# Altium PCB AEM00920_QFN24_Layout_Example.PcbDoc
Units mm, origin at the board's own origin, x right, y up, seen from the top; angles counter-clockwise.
Board outline 76 x 49 mm, 4 copper layers (Component Side, Ground Plane, Power Plane, Solder Side), stack 1.563 mm thick; 11 components, 22 nets, 46 pads, 22 vias.
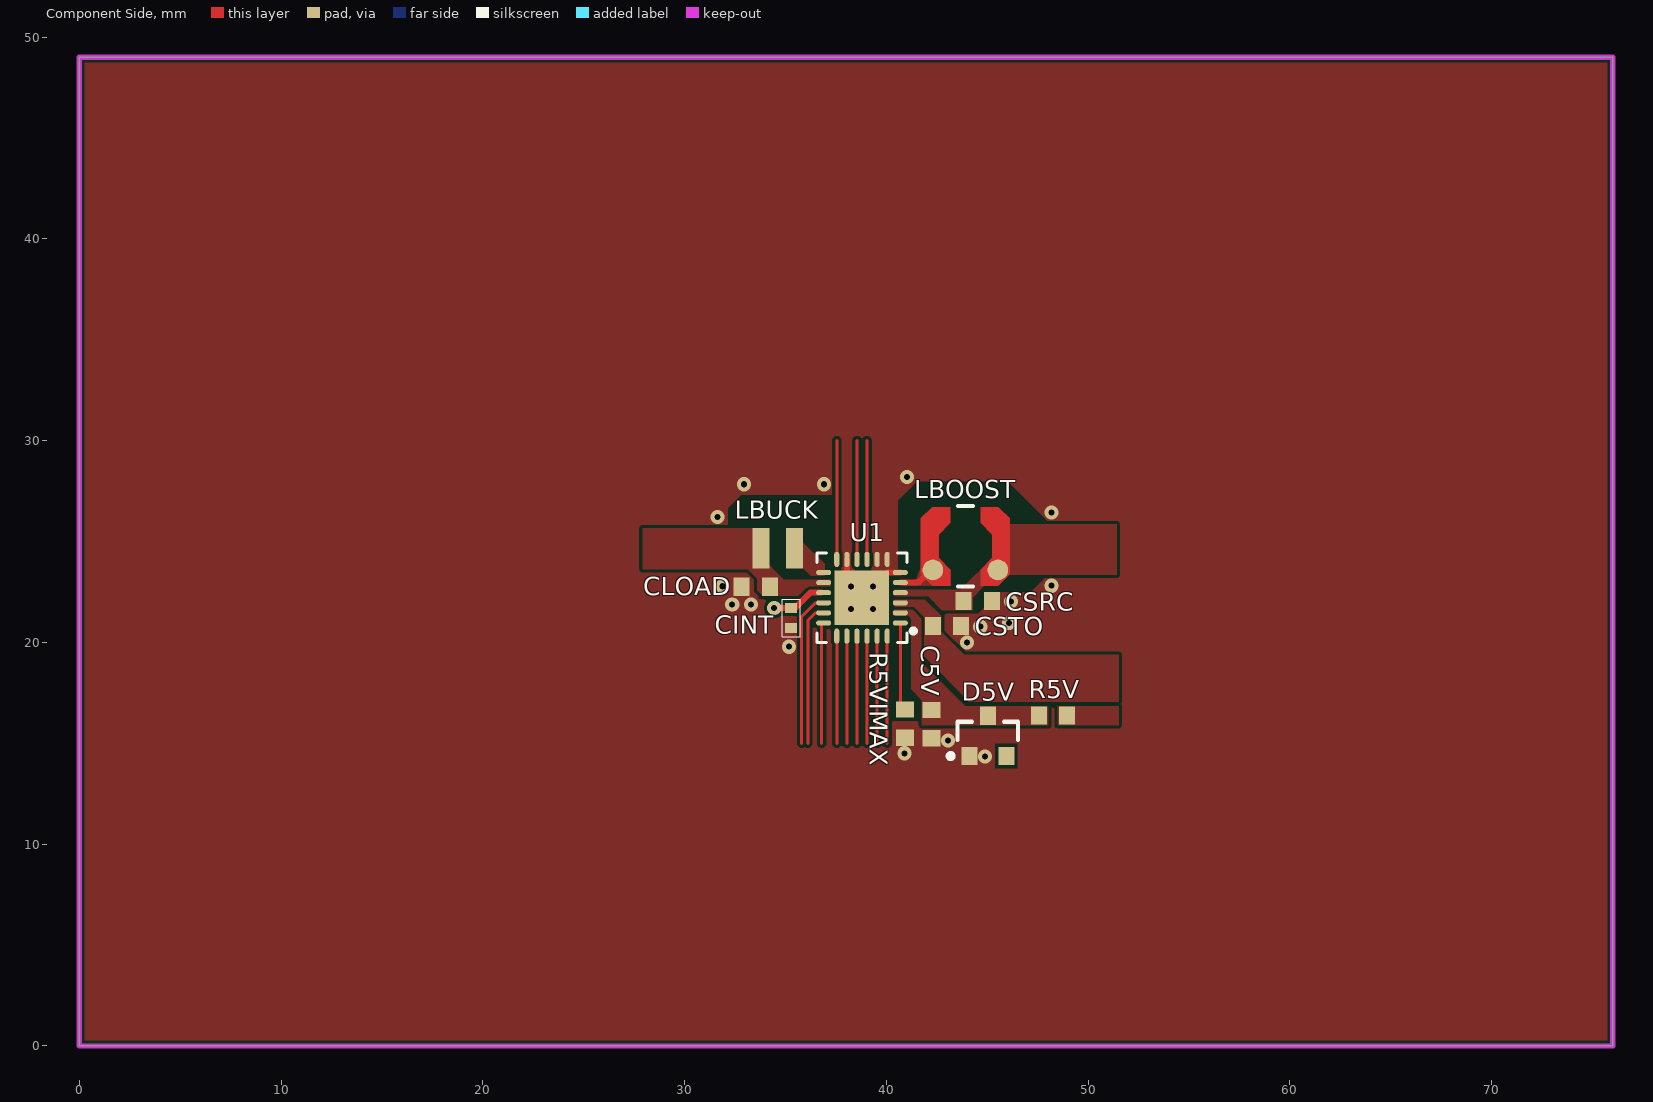
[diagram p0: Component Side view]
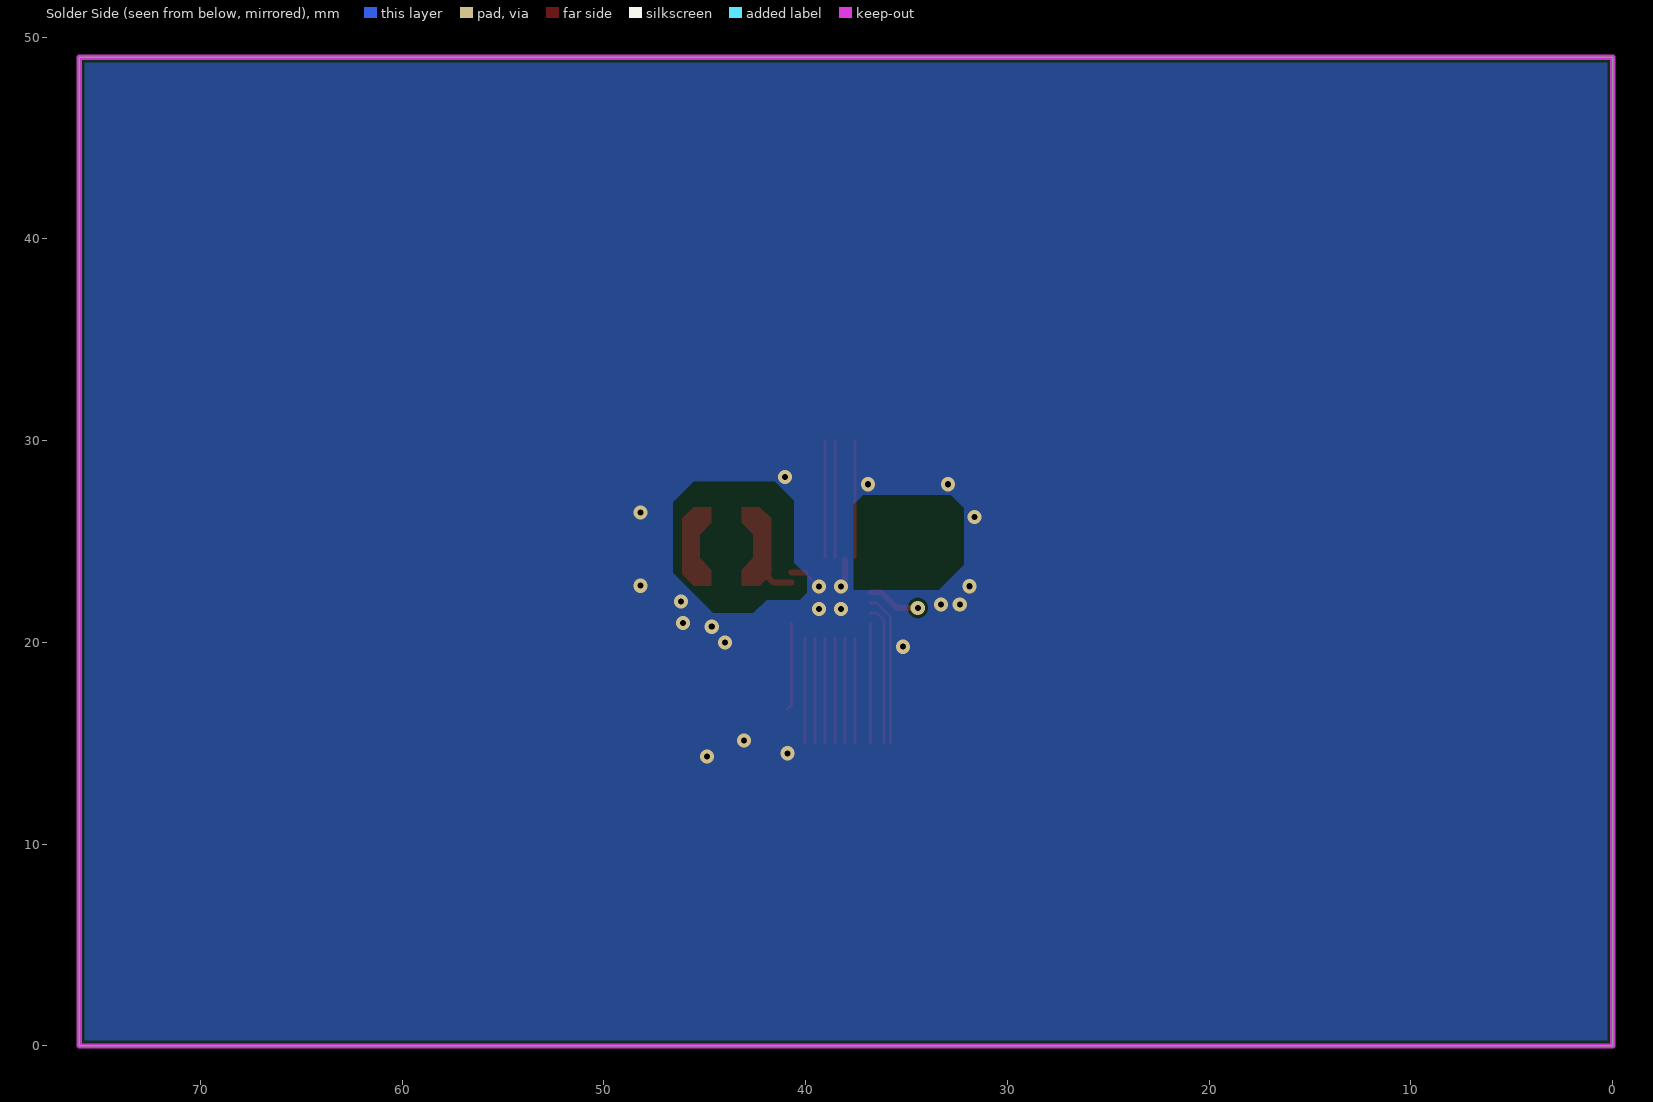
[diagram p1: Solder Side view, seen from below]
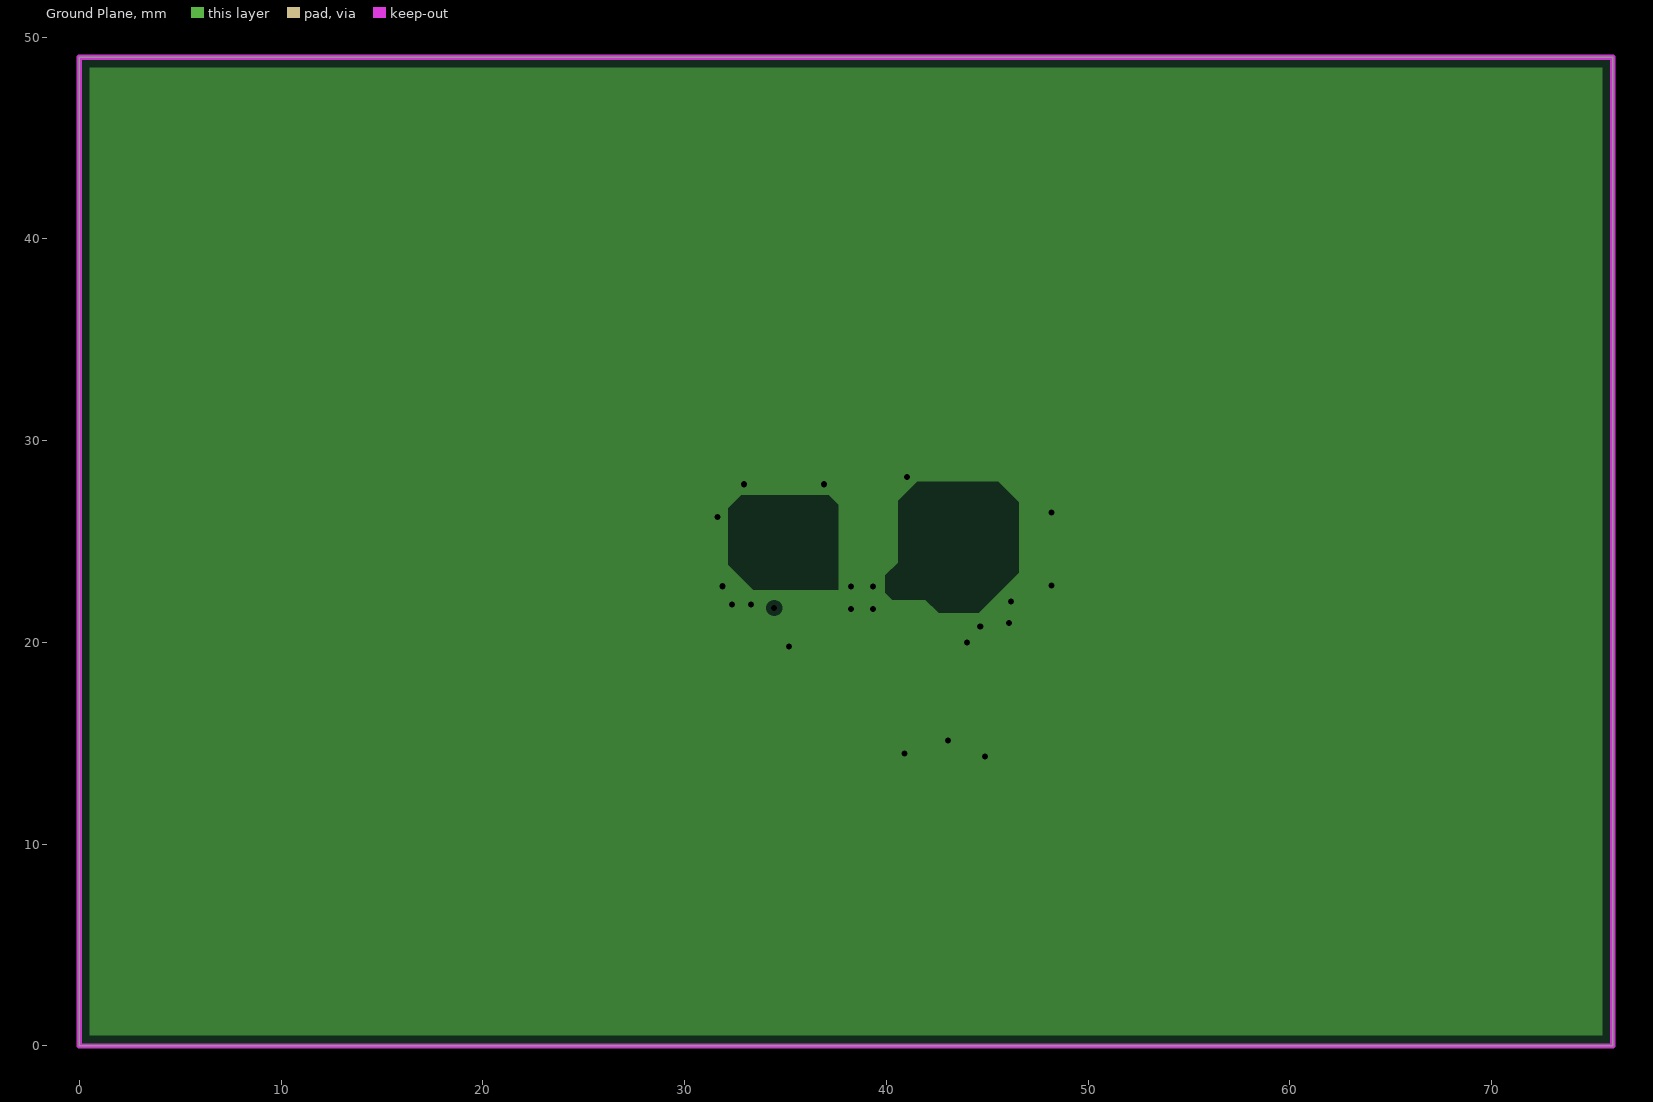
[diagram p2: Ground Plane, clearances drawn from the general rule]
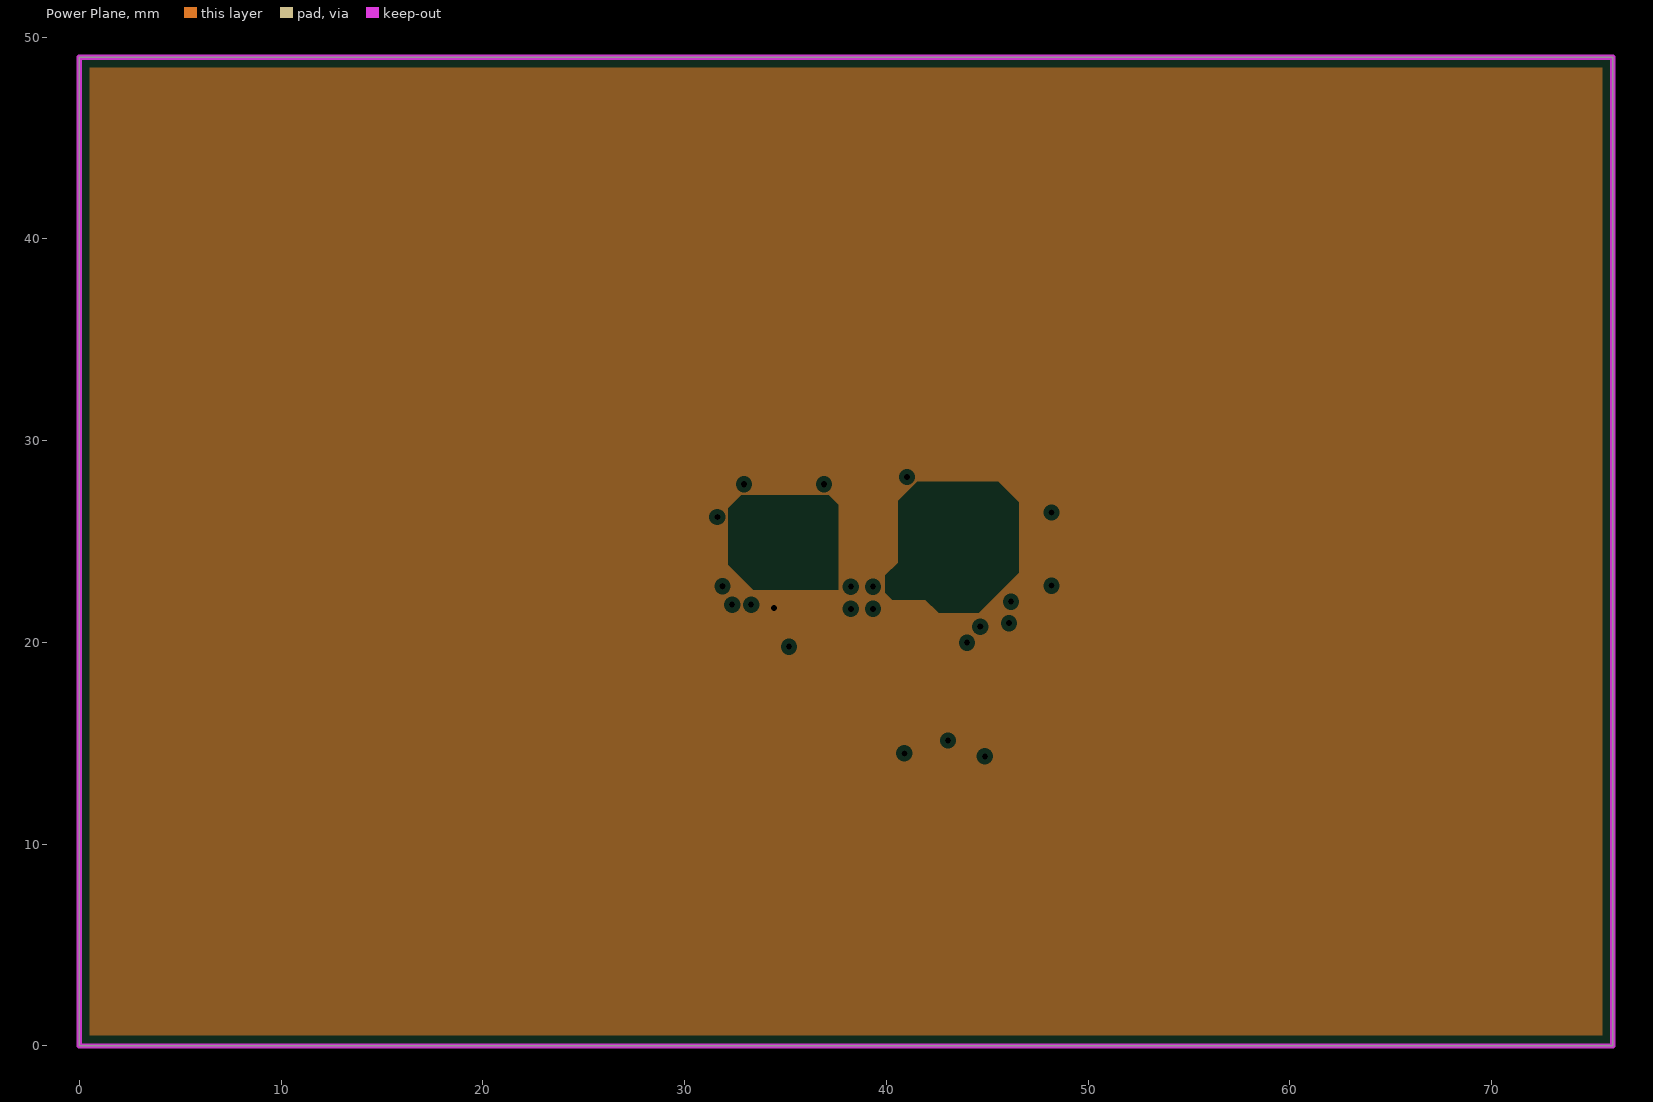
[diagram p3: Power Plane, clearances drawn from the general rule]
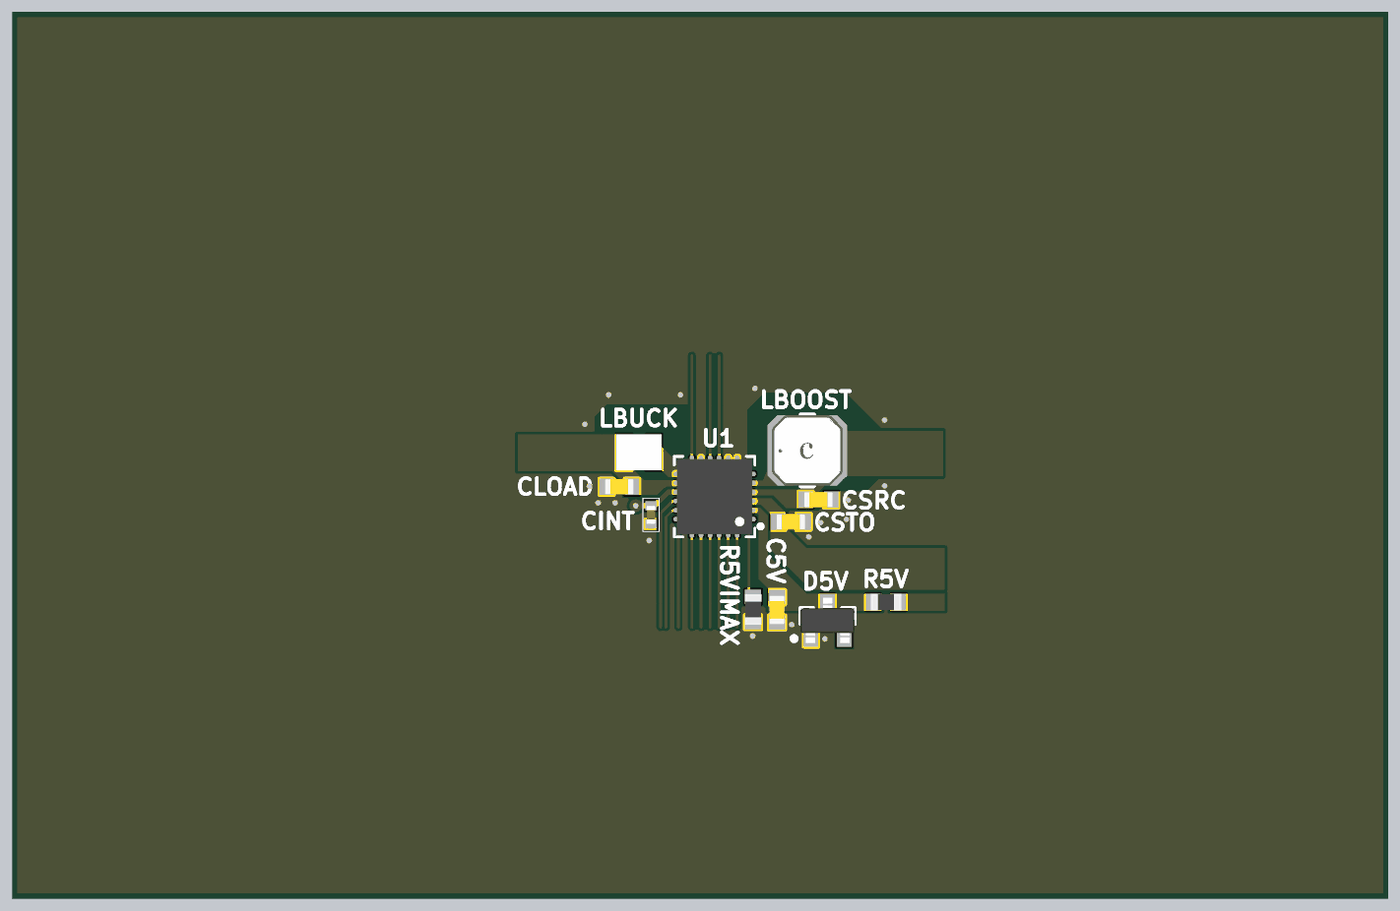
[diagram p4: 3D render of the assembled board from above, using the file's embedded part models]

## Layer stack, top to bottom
Top Solder: solder mask 0.0102, Solder Resist, Dk 3.5
Component Side: signal copper 0.0356
Dielectric 1: prepreg 0.36, Prepreg 7628, Dk 4.2
Ground Plane: plane copper 0.036, net GND
Dielectric 3: core 0.7, Core, Dk 4.2
Power Plane: plane copper 0.036, net VINT
Dielectric 4: prepreg 0.36, Prepreg 7628, Dk 4.2
Solder Side: signal copper 0.0356
Bottom Solder: solder mask 0.0102, Solder Resist, Dk 3.5

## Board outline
0,0 0,49 76,49 76,0

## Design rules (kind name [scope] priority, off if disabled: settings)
Clearance Clearance_SW [InNet('SWBOOST') or InNet('SWBUCK') vs InNet('GND')] p1: gap=0.15 ignorepadtopadclearanceinfootprint=FALSE except(0.5: Arc-Poly Track-Poly SMDPad-Poly THPad-Poly Via-Poly Fill-Poly Poly-Poly Poly-Region)
Clearance [All] p2: gap=0.15 ignorepadtopadclearanceinfootprint=FALSE
ComponentClearance ComponentClearance_DIL [HasFootprint('DIL_PAD') vs HasFootprint('DIL_PAD')] p1: gap=0 collisioncheckmode=3 verticalgap=0 showdistances=FALSE
ComponentClearance [All] p2: gap=0.254 collisioncheckmode=3 verticalgap=0.254 showdistances=FALSE
DiffPairsRouting [All] p1: maxlimit=0.254 minlimit=0.254 mostfreqgap=0.254 toplayer_minwidth=0.381 toplayer_maxwidth=0.381 toplayer_prefwidth=0.381 bottomlayer_minwidth=0.381 bottomlayer_maxwidth=0.381 bottomlayer_prefwidth=0.381 substack1={24748C9E-C2FE-4590-BE0C-AD6E21E98903} toplayer_{24748c9e-c2fe-4590-be0c-ad6e21e98903}_minwidth=0.381 toplayer_{24748c9e-c2fe-4590-be0c-ad6e21e98903}_maxwidth=0.381 toplayer_{24748c9e-c2fe-4590-be0c-ad6e21e98903}_prefwidth=0.381 bottomlayer_{24748c9e-c2fe-4590-be0c-ad6e21e98903}_minwidth=0.381 bottomlayer_{24748c9e-c2fe-4590-be0c-ad6e21e98903}_maxwidth=0.381 bottomlayer_{24748c9e-c2fe-4590-be0c-ad6e21e98903}_prefwidth=0.381 substack2={CAEF0C9C-1F67-4FFA-A1CA-0FD6FF6C2F90} toplayer_{caef0c9c-1f67-4ffa-a1ca-0fd6ff6c2f90}_minwidth=0.381 toplayer_{caef0c9c-1f67-4ffa-a1ca-0fd6ff6c2f90}_maxwidth=0.381 toplayer_{caef0c9c-1f67-4ffa-a1ca-0fd6ff6c2f90}_prefwidth=0.381 bottomlayer_{caef0c9c-1f67-4ffa-a1ca-0fd6ff6c2f90}_minwidth=0.381 bottomlayer_{caef0c9c-1f67-4ffa-a1ca-0fd6ff6c2f90}_maxwidth=0.381 bottomlayer_{caef0c9c-1f67-4ffa-a1ca-0fd6ff6c2f90}_prefwidth=0.381 substack3={D99B185B-21CD-406C-9F05-D1849F64E374} toplayer_{d99b185b-21cd-406c-9f05-d1849f64e374}_minwidth=0.381 toplayer_{d99b185b-21cd-406c-9f05-d1849f64e374}_maxwidth=0.381 toplayer_{d99b185b-21cd-406c-9f05-d1849f64e374}_prefwidth=0.381 bottomlayer_{d99b185b-21cd-406c-9f05-d1849f64e374}_minwidth=0.381 bottomlayer_{d99b185b-21cd-406c-9f05-d1849f64e374}_maxwidth=0.381 bottomlayer_{d99b185b-21cd-406c-9f05-d1849f64e374}_prefwidth=0.381 maxuncoupledlength=12.7
HoleToHoleClearance [All] p1: gap=0.2 allowstackedmicrovias=TRUE
MinimumAnnularRing [All] p1: minimumring=0.15
MinimumSolderMaskSliver [All] p1: minsoldermaskwidth=0
PlaneClearance [All] p1: clearance=0.254
PlaneConnect "Plane Force direct connect" [InComponent('M1') or InComponent('M2') or InComponent('M3') or InComponent('M4') or InComponent('TP1') or InComponent('TP2') or InComponent('TP3')] p1: planeconnectstyle=Direct reliefexpansion=0.508 reliefentries=4 reliefconductorwidth=0.5 reliefairgap=0.254
PlaneConnect [All] p2: pad.planeconnectstyle=Relief pad.reliefexpansion=0.2 pad.reliefentries=4 pad.reliefconductorwidth=0.5 pad.reliefairgap=0.15 via.planeconnectstyle=Direct via.reliefexpansion=0.2 via.reliefentries=4 via.reliefconductorwidth=0.254 via.reliefairgap=0.15
PolygonConnect "Poly Force direct connect" [InComponent('M1') or InComponent('M2') or InComponent('M3') or InComponent('M4')] p1: connectstyle=Direct reliefconductorwidth=0.254 reliefentries=4 polygonreliefangle="90 Angle" airgapwidth=0.254
PolygonConnect [All] p2: thpad.connectstyle=Relief thpad.reliefconductorwidth=0.35 thpad.reliefentries=4 thpad.polygonreliefangle="90 Angle" thpad.airgapwidth=0.15 smdpad.connectstyle=Direct smdpad.reliefconductorwidth=0.5 smdpad.reliefentries=4 smdpad.polygonreliefangle="90 Angle" smdpad.airgapwidth=0.15 via.connectstyle=Direct via.reliefconductorwidth=0.35 via.reliefentries=4 via.polygonreliefangle="90 Angle" via.airgapwidth=0.15
RoutingVias [All] p1: holewidth=0.3 width=0.7 viastyle="Through Hole" minholewidth=0.3 minwidth=0.7 maxholewidth=0.3 maxwidth=0.7
SilkToSilkClearance [All] p1: silktosilkclearance=0
SilkToSolderMaskClearance [IsPad] p1: minsilkscreentomaskgap=0.1 clearancetoexposedcopper=TRUE
SolderMaskExpansion "tented vias" [IsVia] p1: expansion=0.15 istentingtop=TRUE
SolderMaskExpansion [All] p2: expansion=0.11 istentingtop=FALSE
SupplyNets "Schematic Supply Nets_2" [InNet('STO')] p1: voltage=0.000
SupplyNets "Schematic Supply Nets_1" [InNet('GND')] p2: voltage=0.000
SupplyNets "Schematic Supply Nets" [InNet('VINT')] p3: voltage=0.000
Width [All] p1: maxlimit=2 minlimit=0.15 preferedwidth=0.2 substack1={24748C9E-C2FE-4590-BE0C-AD6E21E98903} substack2={CAEF0C9C-1F67-4FFA-A1CA-0FD6FF6C2F90} substack3={D99B185B-21CD-406C-9F05-D1849F64E374} minimp=50.000000 maximp=50.000000 favimp=50.000000
22 further rules are at their usual default settings.

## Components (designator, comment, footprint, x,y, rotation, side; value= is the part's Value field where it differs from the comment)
C5V "Cap Ceramic 0603 TBD" 0603_[1608] 42.24,15.951 r90 top value=TBD
CINT "10uF" 0402_[1005] 35.281,21.209 r90 top
CLOAD "22uF" 0603_[1608] 33.528,22.758 r0 top
CSRC "22uF" 0603_[1608] 44.531,22.047 r180 top
CSTO "47uF" 0603_[1608] 43.007,20.821 r180 top
D5V "5V1" "SOT23-3P  3x1.40mm Pitch=0.915mm diode AK" 45.034,15.367 r90 top
LBOOST "33uH" Coilcraft-LPS4018 43.917,24.765 r0 top
LBUCK "10µH" inductor_2520 34.62,24.663 r0 top
R5V "TBD" Resistor_0603_[1608] 48.26,16.383 r180 top
R5VIMAX "TBD" Resistor_0603_[1608] 40.919,15.977 r90 top
U1 "AEM00920_QFN24" QFN24_4x4mm_PITCH_0.5mm_PAD_2.7mm_QP235-00052 38.792,22.213 r180 top

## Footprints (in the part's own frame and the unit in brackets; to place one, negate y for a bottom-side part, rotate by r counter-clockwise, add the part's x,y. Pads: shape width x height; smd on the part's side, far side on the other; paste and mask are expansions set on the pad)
0402_[1005] [mm] "Chip Capacitor, Body 1.0x0.5mm, IPC High Density"
  rect 0.5x0.6 smd: 1(-0.5,0) 2(0.5,0)
  silkscreen extent -0.92,-0.45 0.92,0.45, body extent -0.5,-0.25 0.5,0.25, height 0.7
0603_[1608] [mm] "Chip Capacitor, Body 1.6x0.8mm, IPC High Density"
  rect 0.8x0.9 smd: 1(-0.7,0) 2(0.7,0)
  body extent -0.8,-0.43 0.8,0.43, height 0.8
Coilcraft-LPS4018 [mm]
  round 1.026 smd paste+0 mask+0: 1(-1.611,-1.175) 2(1.611,-1.175)
  Component Side region: 0.75,1.945 1.64,1.945 2.2,1.395 2.2,-1.395 1.64,-1.945 0.75,-1.945 0.75,-1.17 1.33,-0.575 1.33,0.575 0.75,1.17
  Component Side region: -0.75,1.945 -1.64,1.945 -2.2,1.395 -2.2,-1.395 -1.64,-1.945 -0.75,-1.945 -0.75,-1.17 -1.33,-0.575 -1.33,0.575 -0.75,1.17
  silkscreen extent -0.37,-1.99 0.37,1.99, body extent -2.3,-2.09 2.3,2.09, height 0.25
inductor_2520 [mm]
  rect 0.85x2 smd: 1(-0.825,0) 2(0.825,0)
  body extent -1.25,-1 1.25,1, height 1.19
QFN24_4x4mm_PITCH_0.5mm_PAD_2.7mm_QP235-00052 [mm] "QFN, 24-Leads, Body 4.00x4.00mm, Pitch 0.50mm, Thermal Pad 2.70x2.70mm, IPC High Density"
  oval 0.75x0.25 smd: 1(-1.9,1.25) 2(-1.9,0.75) 3(-1.9,0.25) 4(-1.9,-0.25) 5(-1.9,-0.75) 6(-1.9,-1.25) 13(1.9,-1.25) 14(1.9,-0.75) 15(1.9,-0.25) 16(1.9,0.25) 17(1.9,0.75) 18(1.9,1.25)
  oval 0.25x0.75 smd: 7(-1.25,-1.9) 8(-0.75,-1.9) 9(-0.25,-1.9) 10(0.25,-1.9) 11(0.75,-1.9) 12(1.25,-1.9) 19(1.25,1.9) 20(0.75,1.9) 21(0.25,1.9) 22(-0.25,1.9) 23(-0.75,1.9) 24(-1.25,1.9)
  rect 2.7x2.7 smd: 25(0,0)
  silkscreen extent -2.64,-2.23 2.23,2.22, body extent -2.08,-2.08 2.08,2.08, height 1
Resistor_0603_[1608] [mm]
  rect 0.8x0.9 smd: 1(-0.7,0) 2(0.7,0)
  body extent -0.85,-0.46 0.85,0.46, height 0.56
"SOT23-3P  3x1.40mm Pitch=0.915mm diode AK" [mm] "SOT23, 3-Leads, Body 3x1.40mm, Pitch 0.915mm"
  rect 0.9x0.8 smd: A(-1,0.915) K(1,0) NC(-1,-0.915)
  silkscreen extent -1.12,-1.5 0.7,1.97, body extent -1.25,-1.5 1.25,1.5, height 1.1

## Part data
C5V: Package=0603, Package Metric=1608
CINT: library part "Cap Ceramic 10uF, 6.3V, 20%, X5R, 0402", "Cap Ceramic 10uF, 6.3V, 20%, X5R, 0402", Manuf=MURATA, Manuf PN=GRM155R60J106ME44D, Package=0402, Package Metric=1005
CLOAD CSRC: library part "Cap Ceramic 22uF, 10V, 20%, X5R 0603", "Cap Ceramic 22uF, 10V, 20%, X5R 0603", Manuf=MuRata, Manuf PN=GRM188R61A226ME15D, Package=0603, Package Metric=1608
CSTO: library part "Cap Ceramic 47uF 6.3V +/-20% X5R 0603", "Cap Ceramic 47uF 6.3V +/-20% X5R 0603", Manuf=Murata, Manuf PN=GRM188R60J476ME15D, Package=0603, Package Metric=1608
D5V: library part "Zener 5.1V 350mW BZX84C5V1-TP", "Zener Diode 5.1 V 350 mW ±5% Surface Mount SOT-23", Manuf="Micro Commercial Co", Manuf PN=BZX84C5V1-TP
LBOOST: library part "Power Inductor 33uH - 0,68A - LPS4018 - Small Symbol", "Power Inductor 33uH - 0,68A - LPS4018", Manuf=Coilcraft, Manuf PN=LPS4018-333MRB, Max DC Current=800mA, Package="4 x 4 x 1.8mm", Self Resonant Frequency=20MHz
LBUCK: library part "Power Inductor 10µF TDK VLS-CX-1", "Power Inductor 10µF TDK VLS-CX-1", Manuf=TDK, Manuf PN=VLS252012CX-100M-1, Max DC Current="970 mA", Package=2520
R5V R5VIMAX: library part "Resistor TBD - 0603", "Resistor TBD - 0603", Package=0402
U1: library part "AEM00920 QFN24", Manuf=e-peas, Manuf PN=10AEM00920A0000, Package=QFN24

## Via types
v1: diameter 0.7, hole 0.3, Component Side to Solder Side, tented both sides, 22 vias

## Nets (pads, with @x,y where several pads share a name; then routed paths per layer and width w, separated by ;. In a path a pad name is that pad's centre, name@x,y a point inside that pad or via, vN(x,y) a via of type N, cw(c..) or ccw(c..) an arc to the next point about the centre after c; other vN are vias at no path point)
5V_IMAX: R5VIMAX.2 U1.1 | length 4.4
  Component Side w0.15: U1.1 40.692,16.904 R5VIMAX.2
5V_IN: C5V.2 D5V.K R5V.2 U1.2
5V_IN_EXT: R5V.1
BOOST_CFG: U1.16 | length 7.6
  Component Side w0.15: 35.806,15 35.806,21.282 36.487,21.963 U1.16@36.792,21.963
GND: C5V.1 CINT.1 CLOAD.1 CSRC.1 CSTO.1 D5V.A R5VIMAX.1 U1.6 U1.7 U1.8 U1.11 U1.25 | length 3.2
  Component Side w0.15: v1(39.342,22.763) U1.25@40.042,23.463 ; U1.6 U1.6@40.792,23.463
  Component Side w0.2: U1.25@38.042,22.963 v1(38.242,22.763)
  Component Side w0.3: U1.25@38.042,22.963 U1.11 ; U1.25@40.042,23.463 U1.6
  other v1: 44.882,14.351 40.894,14.503 43.053,15.138 35.179,19.787 43.993,19.99 44.653,20.777 46.076,20.955 38.242,21.663 39.342,21.663 32.36,21.869 33.299,21.869 46.177,22.022 31.877,22.784 48.184,22.809 31.623,26.213 48.184,26.441 32.944,27.838 36.906,27.838 41.021,28.194
LOAD: CLOAD.2 LBUCK.1 U1.14
LOAD_CFG0: U1.19 | length 5.2
  Component Side w0.15: 37.542,15 U1.19@37.542,20.213
LOAD_CFG1: U1.12 | length 5.8
  Component Side w0.15: U1.12@37.542,24.213 37.542,30
SHIP_MODE: U1.9 | length 5.8
  Component Side w0.15: U1.9@39.042,24.213 39.042,30
SRC: CSRC.2 LBOOST.2 U1.4
SRC_LVL_CFG_0: U1.20 | length 5.2
  Component Side w0.15: 38.042,15 U1.20@38.042,20.213
SRC_LVL_CFG_1: U1.21 | length 5.2
  Component Side w0.15: 38.542,15 U1.21@38.542,20.213
SRC_LVL_CFG_2: U1.22 | length 5.2
  Component Side w0.15: 39.042,15 U1.22@39.042,20.213
SRC_LVL_CFG_3: U1.23 | length 5.2
  Component Side w0.15: 39.542,15 U1.23@39.542,20.213
SRC_LVL_CFG_4: U1.24 | length 5.2
  Component Side w0.15: 40.042,15 U1.24@40.042,20.213
ST_STO: U1.10 | length 5.8
  Component Side w0.15: U1.10@38.542,24.213 38.542,30
STO: CSTO.2 U1.3
STO_CFG0: U1.17 | length 6.9
  Component Side w0.15: 36.106,15 36.106,21.082 36.487,21.463 U1.17@36.792,21.463
STO_CFG1: U1.18 | length 6
  Component Side w0.15: 36.792,15 U1.18@36.792,20.963
SWBOOST: LBOOST.1 U1.5 | length 1.9
  Component Side w0.3: U1.5 41.571,22.963 42.198,23.59 LBOOST.1
SWBUCK: LBUCK.2 U1.13
VINT: CINT.2 U1.15 | length 2.7
  Component Side w0.3: v1(34.442,21.709) 35.476,21.709 36.23,22.463 U1.15@36.792,22.463
pads on no net: D5V.NC

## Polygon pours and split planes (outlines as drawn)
SWBOOST on Component Side "NONET_L-01_P-001" (solid, pour order 40): 40.361,23.114 41.427,23.114 41.961,24.155 43.18,23.597 43.18,22.809 42.113,22.809 40.361,22.809
5V_IN_EXT on Component Side "NONET_L-01_P-001" (solid, pour order 57): 48.489,16.84 48.489,15.9 51.511,15.9 51.511,16.84
5V_IN on Component Side "NONET_L-01_P-001" (solid, pour order 35): 41.224,21.184 41.224,17.678 41.758,17.145 41.758,15.9 48.031,15.9 48.031,16.84 43.917,16.84 41.732,19.025 41.732,21.184 41.3,21.615 40.386,21.615 40.31,21.539 40.31,21.387 40.386,21.311 41.097,21.311
GND on Component Side "TOP GND" (solid, remove dead copper, pour order 58): 76,49 0,49 0,0 76,0
STO on Component Side "NONET_L-01_P-001" (solid, pour order 55): 40.361,22.123 41.91,22.123 42.723,21.311 42.723,20.523 43.866,19.38 51.511,19.38 51.511,17.069 44.12,17.069 41.885,19.304 41.885,21.234 41.377,21.742 40.462,21.742 40.361,21.844
LOAD on Component Side "NONET_L-01_P-001" (solid, pour order 47): 37.236,23.114 34.925,23.114 33.795,24.244 33.795,25.565 33.706,25.654 27.915,25.654 27.915,23.63 33.139,23.63 33.604,23.165 33.604,22.581 33.884,22.301 35.662,22.301 36.144,22.784 37.236,22.784
SRC on Component Side "NONET_L-01_P-001" (solid, pour order 53): 43.434,22.606 43.663,22.606 45.237,24.181 45.237,25.349 45.288,25.349 45.796,25.857 51.41,25.857 51.41,23.343 45.39,23.343 44.272,22.225 44.272,21.59 43.917,21.59 43.739,21.768
SWBUCK on Component Side "NONET_L-01_P-001" (solid, pour order 42): 37.236,23.292 36.246,23.292 35.052,24.486 35.56,24.994 35.839,24.994 37.236,23.597
SRC on Component Side "NONET_L-01_P-001" (solid, pour order 39): 40.411,22.276 40.361,22.327 40.361,22.606 44.171,22.606 44.272,22.504 44.272,21.641 44.221,21.59 42.75,21.59 42.064,22.276
GND on Solder Side "TOP GND" (solid, remove dead copper, pour order 56): 76,49 0,49 0,0 76,0
VINT on Power Plane (split plane): 75.49,0.51 0.51,0.51 0.51,48.49 75.49,48.49
GND on Ground Plane (split plane): 75.49,0.51 0.51,0.51 0.51,48.49 75.49,48.49

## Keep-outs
Keep-Out Layer:
  the board outline again, w0.25

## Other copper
Component Side:
  pour cut-out: 37.414,23.622 37.846,23.19 38.252,23.19 38.684,23.622 39.098,23.621 40.31,22.886 40.31,20.701 37.262,20.701 37.262,23.622
  pour cut-out: 32.817,27.305 32.156,26.645 32.156,25.806 36.017,25.806 36.017,25.07 36.874,24.213 37.542,24.213 37.542,27.304 37.541,27.305
  pour cut-out: 41.529,27.965 40.593,27.029 40.593,23.597 41.631,23.597 41.631,26.187 42.215,26.772 45.745,26.772 46.507,26.01 47.981,26.01 46.025,27.965
  pour cut-out: 44.323,22.2 44.882,22.758 45.593,22.758 46.101,23.266 47.93,23.266 47.168,22.504 44.831,22.504 44.831,21.717 44.552,21.438 44.323,21.438
Solder Side:
  pour cut-out: 37.617,22.606 33.401,22.606 32.156,23.851 32.156,26.645 32.817,27.305 37.135,27.305 37.617,26.822
  pour cut-out: 40.297,22.111 41.923,22.111 42.596,21.463 44.577,21.463 46.558,23.444 46.558,26.949 45.542,27.965 41.529,27.965 40.592,27.029 40.592,23.955 39.954,23.317 39.954,22.454
Ground Plane (plane layer: these items are gaps in the copper):
  pour cut-out: 37.617,22.606 33.401,22.606 32.156,23.851 32.156,26.645 32.817,27.305 37.135,27.305 37.617,26.822
  pour cut-out: 40.297,22.111 41.923,22.111 42.596,21.463 44.577,21.463 46.558,23.444 46.558,26.949 45.542,27.965 41.529,27.965 40.592,27.029 40.592,23.955 39.954,23.317 39.954,22.454
Power Plane (plane layer: these items are gaps in the copper):
  pour cut-out: 37.617,22.606 33.401,22.606 32.156,23.851 32.156,26.645 32.817,27.305 37.135,27.305 37.617,26.822
  pour cut-out: 40.297,22.111 41.923,22.111 42.596,21.463 44.577,21.463 46.558,23.444 46.558,26.949 45.542,27.965 41.529,27.965 40.592,27.029 40.592,23.955 39.954,23.317 39.954,22.454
